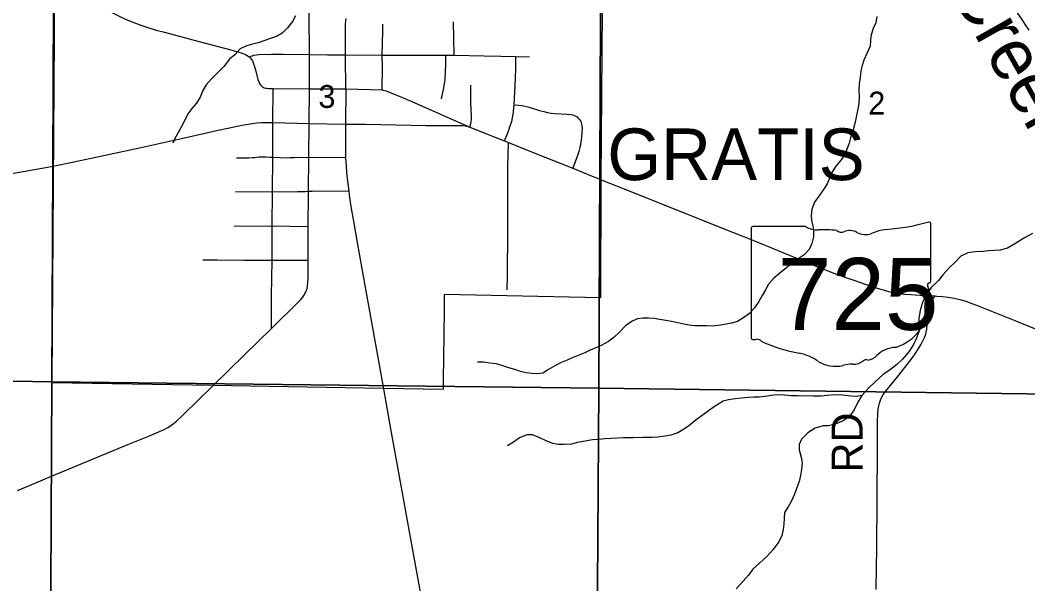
# Model space of a CAD drawing. Extents: x 0 to 34, y 0 to 22.
# Drawn here: x 6.414 to 8.26, y 16.874 to 17.907 of the extents above; entities that cross this region are included whole.
import ezdxf

# ---------------------------------------------------------------- set-up
doc = ezdxf.new("R2010")
doc.units = 0
for name, color, linetype in [('GM_X_City_Street', 7, 'Continuous'), ('GM_X_Corporation', 7, 'Continuous'), ('GM_X_Corporation_Text', 7, 'Continuous'), ('GM_X_County_Road', 7, 'Continuous'), ('GM_X_Major_River', 7, 'Continuous'), ('GM_X_Major_River_Text', 7, 'Continuous'), ('GM_X_Minor_River', 7, 'Continuous'), ('GM_X_Section_Text', 7, 'Continuous'), ('GM_X_State_Location', 7, 'Continuous'), ('GM_X_State_Route', 7, 'Continuous'), ('GM_X_State_Shield', 7, 'Continuous'), ('GM_X_Township_Road', 7, 'Continuous'), ('GM_X_Township_Road_Text', 7, 'Continuous')]:
    doc.layers.add(name, color=color, linetype=linetype)

msp = doc.modelspace()

# ---------------------------------------------------------------- linework, layer by layer
at = {"layer": 'GM_X_City_Street'}
for p, q in [((7.2087, 17.8426), (7.208, 17.9043)), ((6.9426, 17.6561), (7.0102, 17.6553))]:
    msp.add_line(p, q, dxfattribs=at)
for points in [[(7.0769, 17.7794), (7.0776, 17.8218), (7.0774, 17.8427), (7.0782, 17.887), (7.0781, 17.8998)], [(6.8333, 17.8397), (6.8366, 17.8409), (6.8394, 17.8419), (6.8418, 17.8426), (6.8462, 17.8434), (6.8517, 17.844), (6.8745, 17.8445), (6.8955, 17.8449), (6.9441, 17.8441)], [(6.9441, 17.8441), (6.9768, 17.8438), (7.01, 17.8435), (7.0774, 17.8427), (7.0887, 17.8427), (7.1005, 17.8428), (7.1938, 17.8427), (7.2087, 17.8426), (7.2642, 17.8415), (7.2943, 17.841), (7.3222, 17.8404), (7.347, 17.8399)], [(7.1856, 17.7626), (7.1899, 17.7832), (7.1913, 17.7906), (7.1923, 17.7974), (7.1927, 17.8025), (7.1929, 17.8085), (7.1935, 17.8311), (7.1938, 17.8427)], [(7.3009, 17.6858), (7.3082, 17.7035), (7.3118, 17.7134), (7.3144, 17.7215), (7.316, 17.7279), (7.317, 17.7344), (7.3189, 17.7521), (7.3206, 17.7868), (7.3217, 17.8172), (7.3222, 17.8404)], [(6.8747, 17.342), (6.8747, 17.4013), (6.8754, 17.4672), (6.8758, 17.5299), (6.8763, 17.5924), (6.8766, 17.6557), (6.8767, 17.7192), (6.8773, 17.7819)], [(7.0103, 17.781), (7.0769, 17.7794), (7.0792, 17.779), (7.0822, 17.7781), (7.0847, 17.7773), (7.0874, 17.7762), (7.1022, 17.7702), (7.1142, 17.765), (7.137, 17.7553), (7.2377, 17.7112)], [(7.2377, 17.7112), (7.2395, 17.7174), (7.2399, 17.7199), (7.2402, 17.7219), (7.2405, 17.7246), (7.2407, 17.7279), (7.2407, 17.7314), (7.2398, 17.7554), (7.2396, 17.7676), (7.2394, 17.7882)], [(7.3189, 17.7521), (7.3277, 17.7512), (7.3337, 17.7505), (7.3386, 17.7496), (7.3441, 17.7482), (7.35, 17.7464), (7.3654, 17.7416), (7.3732, 17.7394), (7.3798, 17.7379), (7.3866, 17.7368), (7.3934, 17.7362), (7.4162, 17.7349), (7.4224, 17.7342), (7.4266, 17.7333), (7.4295, 17.7324), (7.432, 17.7312), (7.4342, 17.7296), (7.4364, 17.7276), (7.4388, 17.725), (7.4403, 17.7227), (7.4417, 17.7195), (7.4425, 17.7169), (7.4431, 17.7127), (7.4433, 17.7083), (7.4431, 17.7015), (7.4423, 17.6928), (7.441, 17.6826), (7.4394, 17.6739), (7.4376, 17.6665), (7.435, 17.6588), (7.4262, 17.6356)], [(7.3063, 17.4128), (7.3066, 17.4389), (7.3071, 17.519), (7.307, 17.5643), (7.3075, 17.6383), (7.3083, 17.6828)], [(6.8104, 17.6547), (6.8327, 17.6548), (6.8395, 17.655), (6.8439, 17.6553), (6.8476, 17.6559), (6.8515, 17.6564), (6.856, 17.6567), (6.8641, 17.6564), (6.8715, 17.656), (6.8766, 17.6557), (6.8901, 17.6551), (6.9018, 17.6549), (6.9087, 17.6552), (6.9161, 17.6555), (6.9426, 17.6561)], [(6.8082, 17.5928), (6.8763, 17.5924), (6.9222, 17.5928), (6.9358, 17.5929), (6.942, 17.5933)], [(6.942, 17.5933), (6.9487, 17.5938), (6.9582, 17.594), (7.0158, 17.5935)], [(6.806, 17.5295), (6.8758, 17.5299), (6.9414, 17.5291)], [(6.7489, 17.468), (6.7749, 17.4675), (6.8239, 17.4671), (6.8754, 17.4672), (6.9415, 17.4671)]]:
    msp.add_lwpolyline(points, dxfattribs=at)
at = {"layer": 'GM_X_Corporation'}
for points in [[(5.4991, 18.3437), (6.4791, 18.3297), (6.4721, 17.2442), (5.4781, 17.2612)], [(6.4791, 18.3297), (7.4788, 18.3152), (7.4742, 17.2327), (6.4721, 17.2442)], [(8.4911, 18.3026), (8.489, 17.2189), (7.4742, 17.2327), (7.4788, 18.3152)], [(6.4721, 17.2442), (6.4674, 16.2404), (5.4651, 16.258), (5.4781, 17.2612)], [(7.4742, 17.2327), (7.4675, 16.2282), (6.4674, 16.2404), (6.4721, 17.2442)], [(8.489, 17.2189), (8.4859, 16.2068), (7.4675, 16.2282), (7.4742, 17.2327)]]:
    msp.add_lwpolyline(points, close=True, dxfattribs=at)
msp.add_lwpolyline([(7.4829, 18.3159), (7.4779, 17.6151), (7.4772, 17.3982), (7.1909, 17.404), (7.1908, 17.3939), (7.1904, 17.3659), (7.1901, 17.3383), (7.1894, 17.2832), (7.189, 17.2539), (7.1888, 17.2302), (7.0793, 17.2318), (6.7665, 17.2373), (6.472, 17.2423), (6.4739, 17.6399), (6.4752, 17.9391)], dxfattribs=at)
at = {"layer": 'GM_X_County_Road'}
msp.add_line((7.0103, 17.781), (7.01, 17.8396), dxfattribs=at)
msp.add_lwpolyline([(7.01, 17.8396), (7.01, 17.8435), (7.0101, 17.9003), (7.0105, 17.9052), (7.0111, 17.9099)], dxfattribs=at)
at = {"layer": 'GM_X_Major_River'}
msp.add_lwpolyline([(8.2181, 17.9805), (8.2187, 17.9698), (8.2212, 17.9603), (8.2244, 17.95), (8.2299, 17.9393), (8.2354, 17.929), (8.2417, 17.9186), (8.2487, 17.9082), (8.2546, 17.8987), (8.2616, 17.889)], dxfattribs=at)
at = {"layer": 'GM_X_Minor_River'}
for points in [[(6.9182, 17.915), (6.9127, 17.9049), (6.9037, 17.8933), (6.8937, 17.8832), (6.8833, 17.8774), (6.8726, 17.8734), (6.8619, 17.8698), (6.8501, 17.8658), (6.8371, 17.8627), (6.8272, 17.8591), (6.8169, 17.8543), (6.8076, 17.8443), (6.7972, 17.8357), (6.7871, 17.8219), (6.7755, 17.8103), (6.7647, 17.7996)], [(7.9832, 17.9135), (7.9811, 17.9022), (7.9767, 17.8917), (7.9727, 17.8804), (7.9718, 17.8701), (7.9712, 17.8591), (7.9649, 17.846), (7.9593, 17.834), (7.9561, 17.8242), (7.954, 17.814), (7.9527, 17.8019), (7.9509, 17.7901), (7.9503, 17.7788), (7.9508, 17.7651), (7.9499, 17.7534), (7.9448, 17.7262), (7.9423, 17.7152), (7.9391, 17.7035), (7.9351, 17.6911), (7.9322, 17.6813), (7.929, 17.6715), (7.9246, 17.6609), (7.918, 17.6508), (7.9079, 17.6393), (7.9013, 17.6288), (7.8965, 17.6175), (7.8922, 17.607), (7.8855, 17.5965), (7.8769, 17.5845), (7.8692, 17.5733), (7.864, 17.5605), (7.8626, 17.5491), (7.8636, 17.5396), (7.8661, 17.5301), (7.8674, 17.5202), (7.8672, 17.51), (7.864, 17.4979), (7.8592, 17.4866), (7.8503, 17.4769), (7.8392, 17.4695), (7.8276, 17.461), (7.8153, 17.4514), (7.8057, 17.4432), (7.7941, 17.4332), (7.7848, 17.4231), (7.7793, 17.4126), (7.773, 17.4021), (7.7672, 17.3916), (7.759, 17.38), (7.7497, 17.3696), (7.7397, 17.3618), (7.7278, 17.3544), (7.7167, 17.3516), (7.7072, 17.3499), (7.6973, 17.3478), (7.6825, 17.3458), (7.6715, 17.3468), (7.6609, 17.347), (7.6506, 17.3464), (7.6396, 17.3477), (7.6298, 17.3498), (7.6185, 17.3523), (7.6071, 17.3544), (7.5965, 17.3565), (7.5859, 17.3582), (7.5754, 17.3603), (7.5647, 17.3609), (7.5549, 17.3607), (7.5446, 17.3593), (7.535, 17.355), (7.5231, 17.3465), (7.5127, 17.3357), (7.5019, 17.326), (7.4915, 17.3179), (7.4784, 17.3105)], [(6.7647, 17.7996), (6.755, 17.7884), (6.7487, 17.7779), (6.7436, 17.7662), (6.7373, 17.7549), (6.7284, 17.7452), (6.7214, 17.7355), (6.7154, 17.7235), (6.7091, 17.7107), (6.7029, 17.7002), (6.6974, 17.6901), (6.6934, 17.6814)], [(8.2685, 17.5157), (8.2539, 17.5081), (8.2438, 17.5019), (8.2331, 17.4953), (8.2223, 17.4892), (8.2089, 17.4857), (8.1987, 17.4848), (8.188, 17.4839), (8.1778, 17.483), (8.1633, 17.4823), (8.15, 17.4803), (8.137, 17.4746), (8.1264, 17.4634), (8.1156, 17.4531), (8.1039, 17.4401), (8.096, 17.4301), (8.0824, 17.4167), (8.0722, 17.4018), (8.0661, 17.3879), (8.0628, 17.3751), (8.0598, 17.3608), (8.0598, 17.3464), (8.0599, 17.3357), (8.0554, 17.3226), (8.0502, 17.3125), (8.0416, 17.299), (8.0302, 17.2856), (8.0197, 17.276), (8.0081, 17.2668), (7.995, 17.2573), (7.9799, 17.244), (7.9682, 17.2325), (7.9554, 17.2188), (7.9486, 17.2065), (7.9414, 17.1926), (7.9324, 17.1796), (7.9216, 17.1726), (7.9066, 17.1665), (7.8948, 17.1634), (7.8849, 17.1633), (7.8704, 17.1591), (7.8566, 17.1507), (7.8449, 17.1389), (7.8409, 17.1291), (7.841, 17.1192), (7.8444, 17.1059), (7.8461, 17.0963), (7.8454, 17.0835), (7.8436, 17.0725), (7.8411, 17.0616), (7.837, 17.0514), (7.8321, 17.0379), (7.8265, 17.0248), (7.8206, 17.015), (7.8142, 17.0042), (7.8132, 16.9944), (7.8126, 16.983), (7.8119, 16.9735), (7.8094, 16.9626), (7.8034, 16.9506), (7.7928, 16.9361), (7.7819, 16.9238), (7.7683, 16.9116), (7.7563, 16.9009), (7.748, 16.8898), (7.7383, 16.8786), (7.7258, 16.8645)], [(7.4784, 17.3105), (7.4685, 17.3065), (7.4582, 17.3018), (7.4482, 17.2974), (7.4364, 17.2923), (7.4261, 17.2887), (7.4157, 17.284), (7.4039, 17.2789), (7.3943, 17.2741), (7.382, 17.2664), (7.3713, 17.2602), (7.3606, 17.2588), (7.3512, 17.2594), (7.3406, 17.2604), (7.3307, 17.2632), (7.3198, 17.2668), (7.3092, 17.27), (7.2983, 17.2733), (7.2866, 17.2769), (7.2741, 17.2783), (7.2635, 17.28), (7.2518, 17.2802)], [(7.9554, 17.2188), (7.9458, 17.2172), (7.9356, 17.2178), (7.9201, 17.2197), (7.9049, 17.2201), (7.892, 17.2192), (7.8814, 17.218), (7.8673, 17.218), (7.8393, 17.2186), (7.8264, 17.2186), (7.8139, 17.2196), (7.8003, 17.22), (7.7896, 17.2187), (7.7786, 17.2171), (7.7675, 17.2158), (7.758, 17.2157), (7.7478, 17.2156), (7.7353, 17.2144), (7.7238, 17.2131), (7.7113, 17.2111), (7.7017, 17.2083), (7.6902, 17.2014), (7.6798, 17.1945), (7.6678, 17.1853), (7.652, 17.1743), (7.638, 17.1625), (7.628, 17.1559), (7.6184, 17.1508), (7.6061, 17.1462), (7.5913, 17.1439), (7.5818, 17.1426), (7.5715, 17.1418), (7.5552, 17.1418), (7.537, 17.1415), (7.5191, 17.1411), (7.4963, 17.1402), (7.4849, 17.1393), (7.4739, 17.1385), (7.4622, 17.138), (7.445, 17.1346), (7.4351, 17.133), (7.4236, 17.1298), (7.4107, 17.129), (7.3997, 17.1293), (7.3895, 17.131), (7.3787, 17.1355), (7.3659, 17.1415), (7.3524, 17.1467), (7.3418, 17.147), (7.3287, 17.1412), (7.3179, 17.1332), (7.3064, 17.1266)]]:
    msp.add_lwpolyline(points, dxfattribs=at)
at = {"layer": 'GM_X_State_Route'}
for p, q in [((6.9438, 17.7814), (7.0103, 17.781)), ((6.9433, 17.7175), (7.0097, 17.7166)), ((6.4741, 17.6393), (6.4828, 17.6412)), ((7.4747, 17.616), (7.4785, 17.6145)), ((6.7626, 17.2327), (6.767, 17.237))]:
    msp.add_line(p, q, dxfattribs=at)
for points in [[(6.9438, 17.7814), (6.9441, 17.8441), (6.9435, 17.9171), (6.9431, 18.0135), (6.9434, 18.0189), (6.9438, 18.023), (6.9442, 18.0278), (6.9268, 18.0713), (6.9246, 18.0774), (6.9233, 18.0819), (6.9223, 18.0861), (6.9168, 18.1118), (6.8818, 18.3077)], [(6.3872, 18.1128), (6.4186, 18.0659), (6.4486, 18.0265), (6.4576, 18.0162), (6.4665, 18.0067), (6.477, 17.9962), (6.4874, 17.9864), (6.5009, 17.9745), (6.5099, 17.967), (6.5203, 17.9591), (6.5314, 17.9512), (6.5438, 17.943), (6.5525, 17.9376), (6.557, 17.9348), (6.5709, 17.9268), (6.5841, 17.9197), (6.5952, 17.9143), (6.6082, 17.9084), (6.622, 17.9028), (6.6353, 17.8978), (6.6459, 17.8942), (6.6631, 17.889), (6.6785, 17.8848)], [(6.6785, 17.8848), (6.7393, 17.8685), (6.8, 17.8527), (6.8126, 17.849), (6.8209, 17.8463), (6.8239, 17.8451), (6.8266, 17.8439), (6.8299, 17.842), (6.8333, 17.8397), (6.8351, 17.838), (6.8375, 17.8352), (6.8393, 17.8324), (6.841, 17.829), (6.8426, 17.8242), (6.8455, 17.8134), (6.8495, 17.7984), (6.8511, 17.7939), (6.8526, 17.7909), (6.8541, 17.7886), (6.8554, 17.7872)], [(6.8554, 17.7872), (6.856, 17.7865), (6.8578, 17.785), (6.8599, 17.7837), (6.8627, 17.7827), (6.8659, 17.7822), (6.8697, 17.7819), (6.8773, 17.7819), (6.9438, 17.7814)], [(6.9419, 17.5884), (6.942, 17.5933), (6.9426, 17.6561), (6.9433, 17.7175), (6.9438, 17.7814)], [(7.0103, 17.781), (7.0097, 17.7166), (7.0098, 17.6806), (7.0099, 17.6657), (7.01, 17.6601), (7.0102, 17.6553), (7.0106, 17.6465)], [(6.7942, 17.709), (6.7952, 17.7092), (6.814, 17.7133), (6.8274, 17.716), (6.8397, 17.7179), (6.8476, 17.7188), (6.8562, 17.7193), (6.8663, 17.7194), (6.8735, 17.7192)], [(6.4828, 17.6412), (6.5069, 17.6463), (6.6327, 17.673), (6.7098, 17.6899), (6.777, 17.7052), (6.7942, 17.709)], [(6.8735, 17.7192), (6.8767, 17.7192), (6.9433, 17.7175)], [(7.0097, 17.7166), (7.0467, 17.7162), (7.1026, 17.715), (7.1569, 17.7142), (7.2176, 17.7142), (7.2246, 17.7138), (7.2295, 17.7131), (7.2377, 17.7112), (7.2853, 17.6921), (7.3009, 17.6858), (7.3083, 17.6828), (7.3504, 17.6658), (7.4262, 17.6356), (7.4617, 17.6213), (7.4747, 17.616)], [(7.0106, 17.6465), (7.0125, 17.6218), (7.0158, 17.5935), (7.0173, 17.5811), (7.0202, 17.5621), (7.0243, 17.5383), (7.0318, 17.4961), (7.0362, 17.4722), (7.0456, 17.4204), (7.0529, 17.3806), (7.0582, 17.35), (7.0795, 17.2312)], [(5.3748, 17.4428), (5.3907, 17.4459), (5.42, 17.4511), (5.4304, 17.4529), (5.442, 17.4551), (5.4463, 17.456), (5.4567, 17.4578), (5.4683, 17.4598), (5.4809, 17.4622), (5.5766, 17.4785), (5.6733, 17.4951), (5.7149, 17.5026), (5.801, 17.5185), (5.9097, 17.5384), (5.9909, 17.5531), (6.0667, 17.5665), (6.1413, 17.5798), (6.2471, 17.5988), (6.3553, 17.6184), (6.378, 17.6224), (6.4613, 17.637), (6.4741, 17.6393)], [(7.4785, 17.6145), (7.5152, 17.5995), (7.5602, 17.5817), (7.6986, 17.5264), (7.7559, 17.5039), (7.8453, 17.4668), (7.8608, 17.4604), (7.8891, 17.4491), (7.8996, 17.4453), (7.9095, 17.4417), (7.9211, 17.4374), (7.9427, 17.4296), (7.9597, 17.4237), (7.9785, 17.4174), (7.9899, 17.4139)], [(6.9414, 17.5091), (6.9414, 17.5291), (6.9419, 17.5884)], [(6.767, 17.237), (6.8247, 17.2935), (6.8747, 17.342), (6.9234, 17.3898), (6.9282, 17.395), (6.9316, 17.3993), (6.9337, 17.4023), (6.9362, 17.4066), (6.9381, 17.4107), (6.9395, 17.4148), (6.9406, 17.4202), (6.9411, 17.4257), (6.9416, 17.435), (6.9415, 17.4443), (6.9415, 17.4671), (6.9414, 17.5091)], [(7.9899, 17.4139), (7.9946, 17.4125), (8.0048, 17.4097), (8.014, 17.4077), (8.0244, 17.406), (8.0337, 17.4049), (8.0455, 17.4039), (8.0697, 17.4026), (8.0899, 17.4014), (8.0933, 17.4012), (8.1037, 17.4003), (8.1138, 17.3992), (8.1247, 17.3974), (8.135, 17.3951), (8.1443, 17.3925), (8.1543, 17.3891), (8.164, 17.3855)], [(8.164, 17.3855), (8.1659, 17.3848), (8.1992, 17.3714), (8.2387, 17.3551), (8.2882, 17.3352)], [(6.4094, 17.045), (6.4312, 17.0541), (6.4713, 17.0714), (6.6113, 17.1292), (6.651, 17.1453), (6.6693, 17.153), (6.6777, 17.1568), (6.6843, 17.1603), (6.6895, 17.1636), (6.6944, 17.1672), (6.7001, 17.172), (6.7105, 17.1816), (6.7416, 17.212), (6.7626, 17.2327)], [(7.0795, 17.2312), (7.0838, 17.2069), (7.0926, 17.158), (7.1481, 16.8518)]]:
    msp.add_lwpolyline(points, dxfattribs=at)
at = {"layer": 'GM_X_State_Shield'}
for p, q in [((7.7528, 17.5253), (7.7528, 17.3252)), ((7.8525, 17.5287), (7.756, 17.5287)), ((8.0823, 17.429), (8.0823, 17.5337)), ((8.0823, 17.429), (8.0823, 17.429))]:
    msp.add_line(p, q, dxfattribs=at)
for centre, major_axis, start_param, end_param in [((7.9649, 17.8016), (0.3495, 0), 4.814394, 5.042369), ((8.0787, 17.5341), (0.00367, 0), 6.141152, 7.989035), ((7.7565, 17.5257), (0.00382, 0), 1.712693, 3.28349), ((7.8755, 17.552), (0.037, 0), 4.042523, 4.731795), ((7.8878, 17.4164), (0.133, 0), 1.404758, 1.657858), ((7.918, 17.5267), (0.0107, 0), 3.836095, 5.185415), ((7.9337, 17.5036), (0.0222, 0), 0.950623, 2.079405), ((7.9623, 17.5353), (0.0267, 0), 4.081561, 5.145723), ((8.0095, 17.4676), (0.0703, 0), 1.699011, 2.107814), ((8.0815, 17.4213), (0.00568, 0), 1.883978, 3.671073), ((8.0784, 17.4286), (0.00393, 0), 5.05454, 6.418171), ((8.0454, 17.4081), (0.0341, 0), 5.934695, 6.695948), ((8.0955, 17.3852), (0.0248, 0), 2.387724, 3.262537), ((7.9845, 17.3719), (0.0874, 0), 5.101752, 6.440018), ((7.7566, 17.3247), (0.00385, 0), 3.00124, 4.508301), ((7.7571, 17.3452), (0.0294, 0), 4.665946, 4.897461), ((7.7632, 17.3136), (0.0106, 0), 0.519207, 1.627899), ((7.897, 17.4934), (0.2524, 0), 4.195997, 4.488961), ((7.8217, 17.2353), (0.079, 0), 0.823519, 1.323587), ((8.0214, 17.269), (0.0479, 0), 1.647645, 2.488434), ((7.9072, 17.3126), (0.0501, 0), 4.026481, 4.996735), ((7.9361, 17.2434), (0.0412, 0), 1.495662, 1.94098), ((7.9398, 17.2976), (0.0267, 0), 4.691044, 5.507374), ((7.9639, 17.2783), (0.00752, 0), 1.147584, 2.315152), ((7.9607, 17.3058), (0.0282, 0), 4.937069, 5.64225)]:
    msp.add_ellipse(centre, major_axis=major_axis, ratio=0.8, start_param=start_param, end_param=end_param, dxfattribs=at)
at = {"layer": 'GM_X_Township_Road'}
for points in [[(8.0781, 17.3742), (8.0787, 17.3775), (8.0797, 17.3815), (8.0809, 17.3859), (8.083, 17.3908), (8.0857, 17.3953), (8.0899, 17.4014)], [(7.9819, 16.8635), (7.983, 16.9405), (7.984, 17.0256), (7.9845, 17.1256), (7.9843, 17.171), (7.985, 17.1864), (7.9855, 17.1937), (7.9866, 17.2), (7.9878, 17.2048), (7.9897, 17.2107), (7.9919, 17.2156), (7.9948, 17.2207), (7.9988, 17.2263), (8.0129, 17.2432), (8.0236, 17.2561), (8.0433, 17.2816), (8.0507, 17.2916), (8.061, 17.307), (8.0644, 17.3128), (8.0677, 17.3194), (8.0703, 17.3251), (8.0722, 17.3297), (8.0737, 17.3349), (8.0746, 17.3403), (8.0756, 17.35), (8.077, 17.3657), (8.078, 17.3731), (8.0781, 17.3742)], [(6.4665, 16.239), (6.4682, 16.3954), (6.4693, 16.5245), (6.4702, 16.6338), (6.4702, 16.6971), (6.4703, 16.7437), (6.4708, 16.9189), (6.4715, 17.0226), (6.4713, 17.0714)]]:
    msp.add_lwpolyline(points, dxfattribs=at)

# ---------------------------------------------------------------- texts
at = {"layer": 'GM_X_Corporation_Text'}
msp.add_text('GRATIS', height=0.0947, rotation=0, dxfattribs=at).set_placement((7.4895, 17.6138))
at = {"layer": 'GM_X_Major_River_Text'}
msp.add_text('Creek', height=0.09467, rotation=299.4619, dxfattribs=at).set_placement((8.115, 17.9633))
at = {"layer": 'GM_X_Section_Text'}
for s, p in [('3', (6.9603, 17.7462)), ('2', (7.9674, 17.7341))]:
    msp.add_text(s, height=0.0419, rotation=0, dxfattribs=at).set_placement(p)
at = {"layer": 'GM_X_State_Location'}
for s in ['s', 'r']:
    msp.add_text(s, height=0.000189, dxfattribs=at).set_placement((7.9138, 17.4119))
msp.add_text('725', height=0.000189, rotation=0, dxfattribs=at).set_placement((7.847, 17.3981))
at = {"layer": 'GM_X_State_Shield'}
msp.add_text('725', height=0.13184, dxfattribs=at).set_placement((7.8019, 17.3393))
at = {"layer": 'GM_X_Township_Road_Text'}
msp.add_text('RD', height=0.05682, rotation=90, dxfattribs=at).set_placement((7.9571, 17.0779))

doc.saveas('drawing.dxf')
